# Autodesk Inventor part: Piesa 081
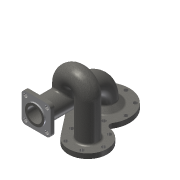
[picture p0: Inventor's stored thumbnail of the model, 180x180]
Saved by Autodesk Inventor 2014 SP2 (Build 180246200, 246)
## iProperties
Created: 2009-02
Part Number: Piesa 081
Document SubType Name: Modeling
Designer: Costel
Material: Steel, Cast
Density: 7.85 g/cm^3
Appearance: Steel - Cast
Author: Costel
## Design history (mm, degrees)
sketch "Sketch1"
  geometry: L1 (-45.5, 78.808)-(0, 0); L2 (-116.594, 0)-(101.287, 0) reference; L3 (0, -73.492)-(0, 191.02) reference; L4 (-86.93, 46.562)-(-31.565, -24.569); A1 r 52.5 centre (-45.5, 78.808) between (-0.533, 51.711) and (-86.93, 46.562); A2 r 8 centre (6.319, 47.582) between (0, 52.489) and (5.266, 39.652); A3 r 40 centre (0, 0) between (-31.565, -24.569) and (5.266, 39.652)
  constraints: 8 point on circle, 4 end point, 4 point on line, 4 tangent, 3 centre point
  dimensions: "d1" = 91 distance of L1.start L1.end; "d2" = 105 diameter of A1; "d3" = 30 deg angle of L3 L1; "d4" = 8 radius of A2; "d6" = 80 diameter of A3
extrude "Extrusion1" new body sketch "Sketch1" distance "d7" = 10; taper "d8" = 0 deg
workaxis "Work Axis1"
workplane "Work Plane1"
sketch "Sketch2"
  geometry: L1 (-1, 0)-(13, 0) reference; L2 (0, 135.939)-(0, -103.892) reference; L3 (10, 32.247)-(10, -52.5) reference; L4 (20, -21.5)-(10, -31.5); L5 (20, -21.5)-(20, 0); L6 (20, 0)-(10, 0); L7 (10, 0)-(10, -31.5); 1 further point
  constraints: 8 end point, 4 point on line, 1 collinear, 1 perpendicular
  dimensions: "d10" = 43 diameter of L4.start L1; "d11" = 45 deg angle of L4 L1; "d12" = 20 distance from line of L2 L4.start
revolve "Revolution1" sketch "Sketch2" stored, may be unused: angle "d13" = 90 deg
sketch "Sketch3"
  geometry: C1 r 21.5 at (0, 0) reference
sketch "Sketch4"
  geometry: L1 (-2, 0)-(26, 0) reference; L2 (20, 21.5)-(20, -21.5) reference; L3 (60, 40)-(60, 140); A1 r 40 centre (20, 40) between (20, 0) and (60, 40)
  constraints: 2 end point, 2 point on circle, 1 centre point, 1 midpoint, 1 parallel, 1 point on line, 1 tangent
  dimensions: "d14" = 40 radius of A1; "d15" = 140 distance from line of L1 L3.end
sweep "Sweep1" sketch "Sketch3", "Sketch4" dims "d16" = 0
sketch "Sketch5"
  geometry: L1 (14, 10)-(77, 10) reference; L2 (-5.266, 10)-(31.565, 10) reference; L3 (0.533, 10)-(-5.266, 10) reference; L4 (86.93, 10)-(0.533, 10) reference; L5 (31.565, 10)-(86.93, 10) reference; L6 (-5.266, 0)-(0.533, 0) reference; L7 (31.565, 0)-(-5.266, 0) reference; L8 (86.93, 0)-(31.565, 0) reference; L9 (0.533, 0)-(86.93, 0) reference; L10 (0, -8.15)-(0, 105.95) reference; L11 (45.5, 60)-(45.5, 85); L12 (0, 85)-(0, 10); C1 r 21.5 at (45.5, 60) reference; C2 r 21.5 at (45.5, 60) reference; A1 r 22.75 centre (22.75, 85) between (45.5, 85) and (0, 85)
  constraints: 4 end point, 2 point on circle, 2 tangent, 1 centre point, 1 horizontal alignment, 1 parallel, 1 point on line
  dimensions: "d17" = 85 distance from line of L9 L11.end
sketch "Sketch6"
  geometry: C1 r 20 at (0, 0); A1 r 40 centre (0, 0) between (-31.565, -24.569) and (5.266, 39.652) reference
  constraints: 1 centre point, 1 coincident
  dimensions: "d18" = 40 diameter of C1
sweep "Sweep2" sketch "Sketch5", "Sketch6" dims "d19" = 0
sketch "Sketch7"
  geometry: L1 (-2, 0)-(26, 0); L2 (20, 21.5)-(20, -21.5); L3 (60, 40)-(60, 140); A1 r 40 centre (20, 40) between (20, 0) and (60, 40)
  constraints: 6 end point, 2 point on circle, 1 centre point, 1 midpoint, 1 parallel, 1 point on line, 1 tangent
  dimensions: "d20" = 40 radius of A1; "d21" = 140 distance from line of L1 L3.end
workplane "Work Plane2"
sketch "Sketch8"
  geometry: C1 r 31.5 at (-45.5, 78.808) reference; C2 r 21.5 at (-45.5, 78.808) reference; C3 r 15 at (-45.5, 78.808)
  constraints: 1 centre point, 1 coincident
  dimensions: "d23" = 30 diameter of C3
sweep "Sweep3" sketch "Sketch8" dims "d24" = 0
sketch "Sketch9"
  geometry: L1 (14, 10)-(77, 10); L2 (-5.266, 10)-(31.565, 10); L3 (0.533, 10)-(-5.266, 10); L4 (86.93, 10)-(0.533, 10); L5 (31.565, 10)-(86.93, 10); L6 (-5.266, 0)-(0.533, 0); L7 (31.565, 0)-(-5.266, 0); L8 (86.93, 0)-(31.565, 0); L9 (0.533, 0)-(86.93, 0); L10 (0, -8.15)-(0, 105.95); L11 (45.5, 60)-(45.5, 85); L12 (0, 85)-(0, 0); L13 (111.8, 0)-(-81.4, 0) reference; C1 r 21.5 at (45.5, 60); C2 r 21.5 at (45.5, 60); A1 r 22.75 centre (22.75, 85) between (45.5, 85) and (0, 85)
  constraints: 24 end point, 3 centre point, 2 point on circle, 2 point on line, 2 tangent, 1 horizontal alignment, 1 parallel
  dimensions: "d25" = 85 distance from line of L9 L11.end
sketch "Sketch10"
  geometry: C1 r 15 at (0, 0); A1 r 40 centre (0, 0) between (-31.565, -24.569) and (5.266, 39.652) reference
  constraints: 1 centre point, 1 coincident
  dimensions: "d26" = 30 diameter of C1
sweep "Sweep4" sketch "Sketch9", "Sketch10" dims "d27" = 0
sketch "Sketch11"
  geometry: L1 (20, 15)-(20, -15) reference; L2 (0, -52.5)-(0, 32.247) reference; L3 (-12.775, 0)-(166.075, 0) reference; L4 (20, -21.5)-(10, -31.5) reference; L5 (20, -15)-(4, -31); L6 (0, -37)-(0, 0); L7 (0, 0)-(20, 0); L8 (20, -15)-(20, 0); L9 (0, -37)-(4, -37); L10 (4, -37)-(4, -31); 1 further point
  constraints: 12 end point, 4 point on line, 3 perpendicular, 1 midpoint, 1 parallel
  dimensions: "d28" = 74 diameter of L9 L3; "d29" = 4 distance of L6.start L9.end
revolve "Revolution2" sketch "Sketch11" stored, may be unused: angle "d30" = 90 deg
sketch "Sketch12"
  geometry: C1 r 15 at (0, 0) reference; C2 r 21.5 at (0, 0) reference; C3 r 20 at (0, 0)
  constraints: 1 centre point, 1 coincident
  dimensions: "d31" = 40 diameter of C3
extrude "Extrusion2" join sketch "Sketch12" distance "d32" = 3; taper "d33" = 0 deg
sketch "Sketch13"
  geometry: L1 (-22, 30)-(22, 30); L2 (30, 22)-(30, -22); L3 (22, -30)-(-22, -30); L4 (-30, -22)-(-30, 22); L5 (-30, 0)-(30, 0); C1 r 20 at (0, 0) reference; C2 r 21.5 at (0, 0) reference; C3 r 4 at (-22, 22); C4 r 4 at (22, 22); C5 r 4 at (22, -22); C6 r 4 at (-22, -22); A1 r 8 centre (-22, 22) between (-22, 30) and (-30, 22); A2 r 8 centre (-22, -22) between (-30, -22) and (-22, -30); A3 r 8 centre (22, 22) between (30, 22) and (22, 30); A4 r 8 centre (22, -22) between (22, -30) and (30, -22); 2 further points
  constraints: 10 end point, 8 centre point, 8 point on circle, 8 tangent, 6 equal radius, 4 coincident, 4 midpoint, 4 point on line, 2 parallel, 2 perpendicular, 1 horizontal
  dimensions: "d34" = 60 distance of point (-30, -30) point (-30, 30); "d35" = 8 radius of A1; "d36" = 8 diameter of C3
extrude "Extrusion3" join sketch "Sketch13" distance "d37" = 8; taper "d38" = 0 deg
sketch "Sketch14"
  geometry: L1 (-116.594, 0)-(101.287, 0) reference; C1 r 20 at (0, 0) reference; 1 further point
  constraints: 1 point on line
  dimensions: "d39" = 33 distance of C1.centre point (33, 0)
hole "Hole1" sketch "Sketch14" at (33, 0) diameter "d40" = 8; stored, may be unused: countersink angle "d44" = 90 deg, drill point angle "d46" = 118 deg; dims "d41" = 6, "d42" = 4, "d43" = 2, "d45" = 8
pattern_circular "Circular Pattern1" dims angle "d48" = 360 deg
sketch "Sketch15"
  geometry: L1 (-45.5, 193.898)-(-45.5, -84.045) reference; C1 r 31.5 at (-45.5, 78.808) reference; 1 further point
  constraints: 1 point on line
  dimensions: "d50" = 45.5 distance of point (-45.5, 124.308) C1.centre
hole "Hole2" sketch "Sketch15" at (-45.5, 124.308) diameter "d51" = 8; stored, may be unused: countersink angle "d55" = 90 deg, drill point angle "d57" = 118 deg; dims "d52" = 6, "d53" = 4, "d54" = 2, "d56" = 8
pattern_circular "Circular Pattern2" dims angle "d59" = 360 deg
fillet "Fillet1" dims "d61" = 4
fillet "Fillet2" dims "d62" = 4
fillet "Fillet3" dims "d63" = 4
body "Solid1"
node "Projected Loop1"
node "Projected Loop2"
node "Projected Loop3"
node "Projected Loop4"
other parameters: "d9" = 0
